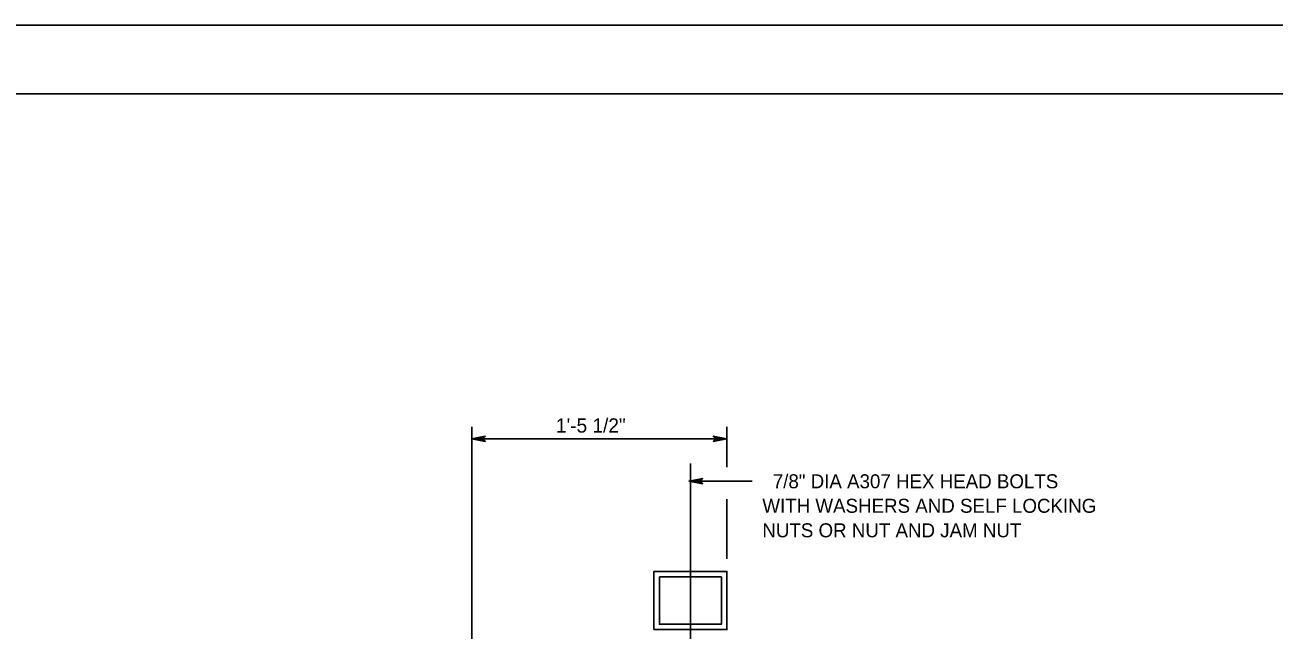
# Model space of a CAD drawing. Extents: x 632007860 to 635435983, y 295418622 to 297794622.
# Drawn here: x 634963261 to 635235396, y 297662745 to 297794622 of the extents above; entities that cross this region are included whole.
import ezdxf

# ---------------------------------------------------------------- set-up
doc = ezdxf.new("R2010")
doc.units = 0
for name, color, linetype in [('1', 7, 'Continuous'), ('8', 7, 'Continuous'), ('PLT-BNDY', 7, 'Continuous'), ('S-DETL-DIMS', 7, 'Continuous'), ('S-DETL-T120', 7, 'Continuous'), ('S-STEL', 7, 'Continuous')]:
    doc.layers.add(name, color=color, linetype=linetype)

msp = doc.modelspace()

# ---------------------------------------------------------------- linework, layer by layer
at = {"layer": '1'}
msp.add_line((634570860, 297779622), (635356860, 297779622), dxfattribs=at)
at = {"layer": '8'}
for p, q in [((635108137, 297663529), (635108138, 297699209)), ((635108137, 297619409), (635108137, 297663626))]:
    msp.add_line(p, q, dxfattribs=at)
at = {"layer": 'PLT-BNDY'}
msp.add_lwpolyline([(634530860, 297794622), (635371860, 297794622), (635371860, 297200622), (634530860, 297200622)], close=True, dxfattribs=at)
at = {"layer": 'S-DETL-DIMS'}
for p, q in [((635060510, 297653050), (635060510, 297707141)), ((635116074, 297698380), (635116074, 297707141)), ((635060511, 297704573), (635116074, 297704573)), ((635107833, 297695360), (635121579, 297695360)), ((635116074, 297678436), (635116074, 297691419))]:
    msp.add_line(p, q, dxfattribs=at)
for points in [[(635060511, 297704573), (635063470, 297705127), (635063356, 297705048), (635063242, 297704969), (635063183, 297704870), (635063124, 297704771), (635063107, 297704672), (635063090, 297704573), (635063107, 297704473), (635063124, 297704374), (635063183, 297704275), (635063242, 297704176), (635063356, 297704097), (635063470, 297704018), (635060511, 297704573), (635063356, 297704097), (635063242, 297704176), (635060511, 297704573), (635063183, 297704275), (635063124, 297704374), (635060511, 297704573), (635063107, 297704473), (635063090, 297704573), (635060511, 297704573), (635063107, 297704672), (635063124, 297704771), (635060511, 297704573), (635063183, 297704870), (635063242, 297704969), (635060511, 297704573), (635063356, 297705048)], [(635116074, 297704573), (635113114, 297704018), (635113228, 297704097), (635113342, 297704176), (635113401, 297704275), (635113460, 297704374), (635113477, 297704473), (635113494, 297704573), (635113477, 297704672), (635113460, 297704771), (635113401, 297704870), (635113342, 297704969), (635113228, 297705048), (635113114, 297705127), (635116074, 297704573), (635113228, 297705048), (635113342, 297704969), (635116074, 297704573), (635113401, 297704870), (635113460, 297704771), (635116074, 297704573), (635113477, 297704672), (635113494, 297704573), (635116074, 297704573), (635113477, 297704473), (635113460, 297704374), (635116074, 297704573), (635113401, 297704275), (635113342, 297704176), (635116074, 297704573), (635113228, 297704097)], [(635107833, 297695360), (635110792, 297695915), (635110678, 297695836), (635110564, 297695757), (635110505, 297695658), (635110447, 297695559), (635110430, 297695460), (635110413, 297695360), (635110430, 297695261), (635110447, 297695162), (635110505, 297695063), (635110564, 297694964), (635110678, 297694885), (635110792, 297694806), (635107833, 297695360), (635110678, 297694885), (635110564, 297694964), (635107833, 297695360), (635110505, 297695063), (635110447, 297695162), (635107833, 297695360), (635110430, 297695261), (635110413, 297695360), (635107833, 297695360), (635110430, 297695460), (635110447, 297695559), (635107833, 297695360), (635110505, 297695658), (635110564, 297695757), (635107833, 297695360), (635110678, 297695836)]]:
    msp.add_lwpolyline(points, dxfattribs=at)
at = {"layer": 'S-STEL'}
for points in [[(635100192, 297675696), (635100192, 297663033)], [(635100192, 297663033), (635116074, 297663033), (635116074, 297675696), (635100192, 297675696), (635100192, 297663033)], [(635101385, 297674504), (635101385, 297664226), (635114881, 297664226), (635114881, 297674504), (635101385, 297674504)]]:
    msp.add_lwpolyline(points, dxfattribs=at)

# ---------------------------------------------------------------- texts
at = {"layer": 'S-DETL-T120'}
for s, height, p in [('1\'-5 1/2"', 3102.3, (635078861, 297705919)), ('  7/8" DIA A307 HEX HEAD BOLTS', 3048.01, (635123793, 297693798)), ('WITH WASHERS AND SELF LOCKING', 3048.01, (635123793, 297688464)), ('NUTS OR NUT AND JAM NUT', 3048.01, (635123793, 297683130))]:
    msp.add_text(s, height=height, dxfattribs=at).set_placement(p)

doc.saveas('drawing.dxf')
